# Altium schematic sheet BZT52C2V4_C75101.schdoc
size 127 x 101 mm
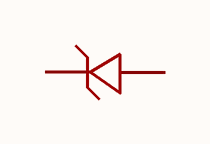
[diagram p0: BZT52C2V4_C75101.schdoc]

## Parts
ZD?  bzt52c2v4_c75101  [SOD-123_L2.8-W1.8-LS3.7-RD]  (value not drawn)

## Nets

Not connected (* = marked no-connect by the designer): ZD? 1(K) 2(A)

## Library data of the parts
ZD? = bzt52c2v4_c75101: 二极管配置:1个独立式;稳压值(标称值):2.4V;稳压值(范围):2.2V~2.6V;耗散功率(Pd):500mW;; Manufacturer: CJ(江苏长电/长晶); AddInBom: yes; ModelId: 7884390a25fb4c08947731ebfba7e3f8; ModelTransform: 144.8816,62.992,0,0,0,0,0,0,0; Diode Configuration: 1个独立式; Zener Voltage(Nom): 2.4V; Reverse Leakage Current (Ir): 50uA; Pd - Power Dissipation: 500mW; Impedance(Zzt): 100Ω; Impedance(Zzk): 600Ω; Operating Junction Temperature Range: -55℃~+150℃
